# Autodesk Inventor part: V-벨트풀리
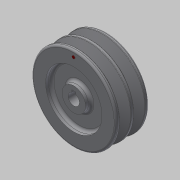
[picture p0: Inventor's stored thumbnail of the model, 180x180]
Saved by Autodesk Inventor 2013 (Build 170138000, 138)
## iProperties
Created: 2016-08
Part Number: V-벨트풀리
Material: 알루미늄 6061
Document SubType Name: Modeling
Designer: mduedu
Density: 2.71 g/cm^3
Mass: 380.117 g
Surface Area: 333.15 cm^2
Volume: 140.265 cm^3
Author: mduedu
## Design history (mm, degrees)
sketch "스케치1"
  geometry: L1 (0, 17.5)-(0, -17.5); L2 (0, -17.5)-(45, -17.5); L3 (45, -17.5)-(45, 17.5); L4 (45, 17.5)-(0, 17.5); L5 (45, -1.524)-(32.5, -5.346); L6 (32.5, -5.346)-(32.5, -9.654); L7 (32.5, -9.654)-(45, -13.476); L8 (45, 13.476)-(32.5, 9.654); L9 (32.5, 9.654)-(32.5, 5.346); L10 (32.5, 5.346)-(45, 1.524); L11 (40.5, 17.5)-(40.5, -17.5); L12 (45, -7.5)-(0, -7.5); L13 (45, 7.5)-(0, 7.5); 8 further points
  constraints: 26 end point, 20 point on line, 6 perpendicular, 3 equal length, 3 midpoint, 2 collinear, 1 coincident, 1 horizontal, 1 vertical
  dimensions: "d43" = 90 diameter of L3 L1; "d45" = 34 deg angle of L7 L5; "d47" = 34 deg angle of L8 L10; "d49" = 9.2 distance of point (40.5, -12.1) point (40.5, -2.9); "d50" = 9.2 distance of point (40.5, 12.1) point (40.5, 2.9) (derived); "d51" = 10 distance between parallel lines of L12 L2; "d52" = 10 distance between parallel lines of L13 L4; "d53" = 15 distance between parallel lines of L12 L13; "d54" = 4.5 distance between parallel lines of L11 L3; "d55" = 8 distance between parallel lines of L6 L11
revolve "회전1" sketch "스케치1" stored, may be unused: angle "d8" = 90 deg
sketch "스케치2"
  geometry: L1 (-2, 0)-(2, 0); L2 (2, 0)-(2, 7.8); L3 (2, 7.8)-(-2, 7.8); L4 (-2, 7.8)-(-2, 0); C1 r 6 at (0, 0); 3 further points
  constraints: 8 end point, 3 coincident, 2 parallel, 1 centre point, 1 horizontal, 1 midpoint, 1 perpendicular
  dimensions: "d9" = 12 diameter of C1; "d11" = 4 distance of L2.end L3.end; "d12" = 7.8 distance of L1.end L2.end
extrude "돌출1" cut sketch "스케치2" stored distance "d13" = 10; taper "d14" = 0 deg
sketch "스케치4"
  geometry: C1 r 30 at (0, 0); C2 r 12.5 at (0, 0); 2 further points
  constraints: 3 coincident, 2 centre point
  dimensions: "d30" = 60 diameter of C1; "d31" = 25 diameter of C2
extrude "돌출2" cut sketch "스케치4" distance "d32" = 6; taper "d33" = 0 deg
fillet "모깎기6" dims "d34" = 3
fillet "모깎기8" dims "d56" = 0.5, "d57" = 1, "d58" = 2
chamfer "모따기1" distance "d26" = 0.5; stored, may be unused: second distance "d27" = 2, angle "d28" = 45 deg
sketch "스케치5" dims "d38" = 78
  geometry: C1 r 1.5 at (0, 39); 3 further points
  constraints: 2 coincident, 2 vertical alignment, 1 centre point, 2 other
  dimensions: "d40" = 3 diameter of C1
extrude "돌출3" join sketch "스케치5" distance "d41" = 0.5; taper "d42" = 0 deg
node "솔리드1"
mirror "대칭2"
